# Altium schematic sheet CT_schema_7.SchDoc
size 369 x 207 mm
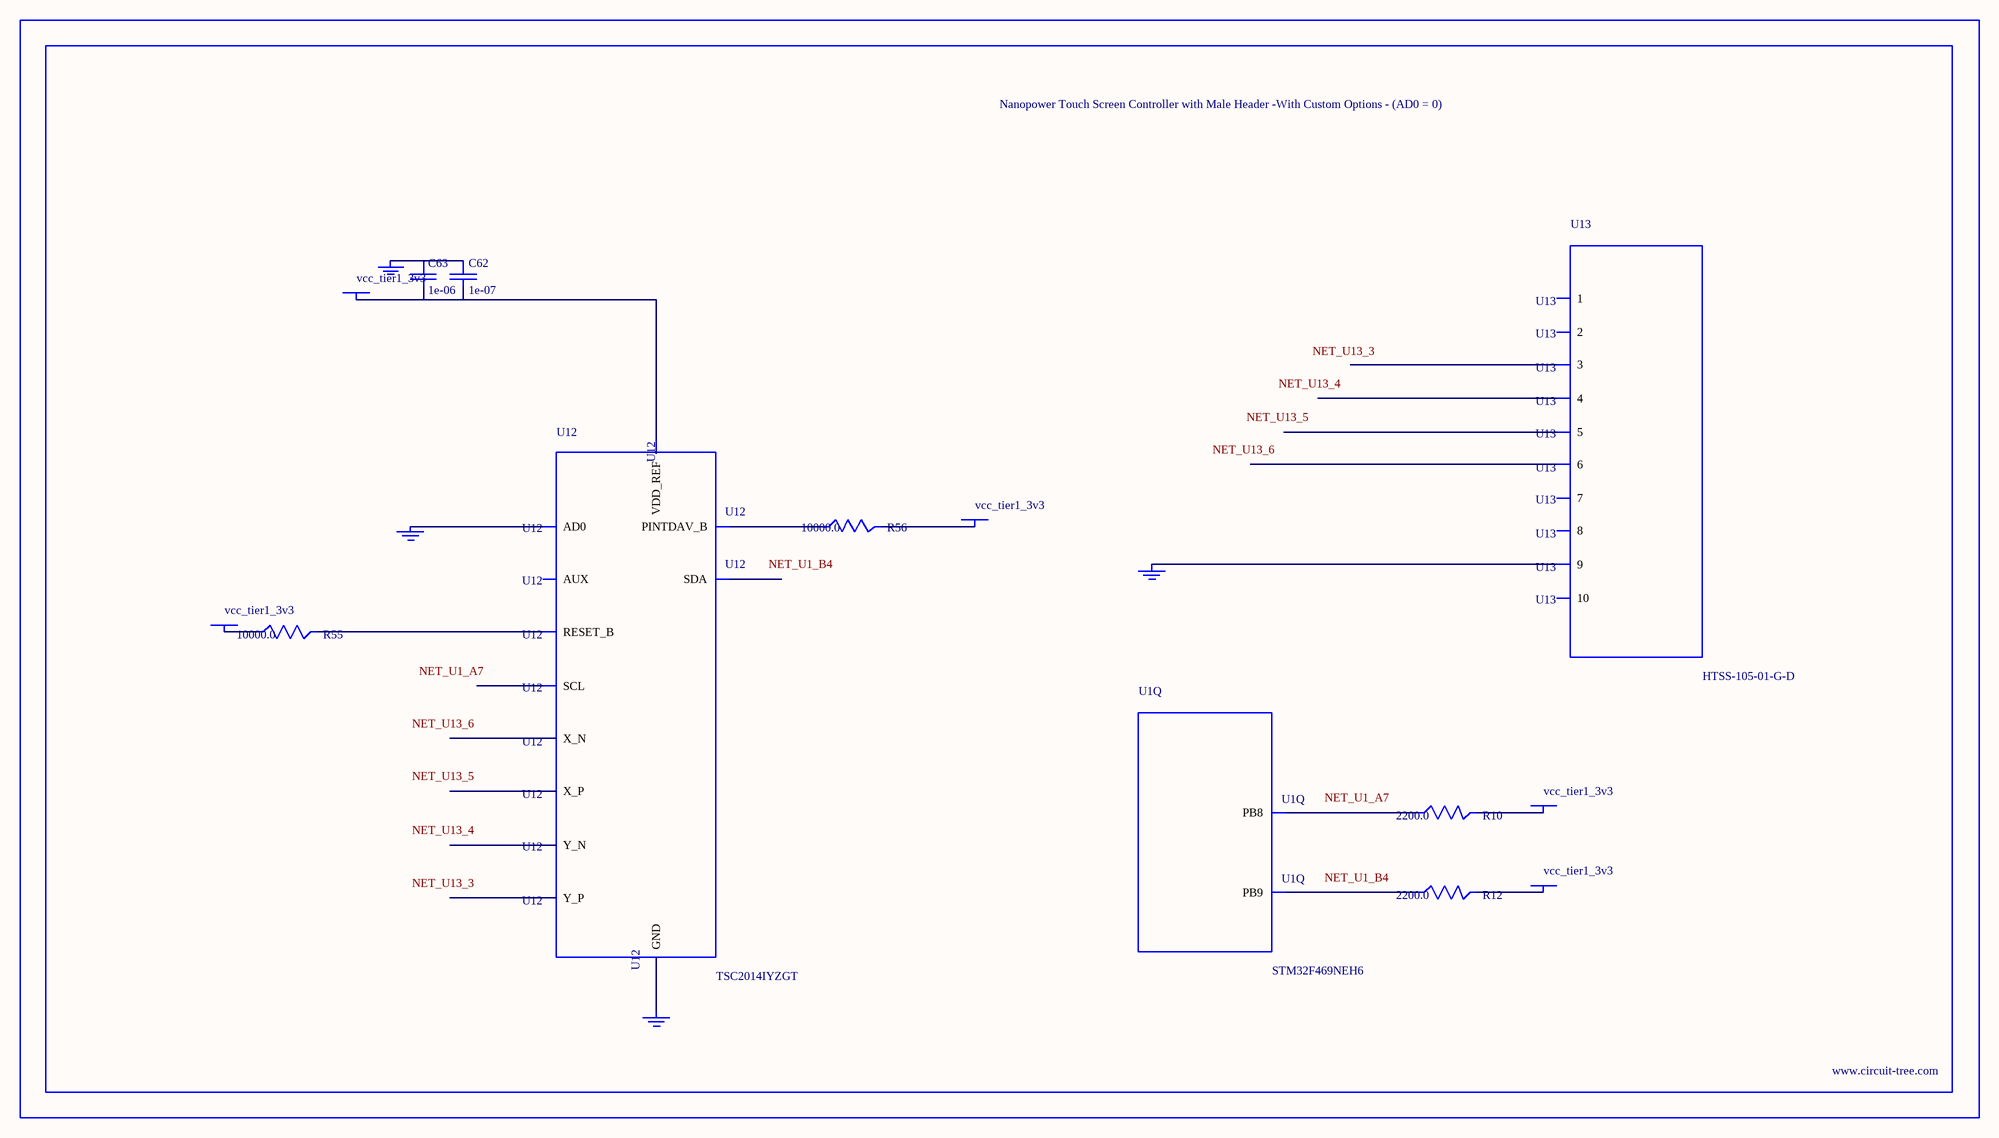
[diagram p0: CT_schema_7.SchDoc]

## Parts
BORDER6  (no value)
C62  1e-07  [C0402]
C63  1e-06  [C0603]
GND_INSTANCE_6_0  (no value)
GND_INSTANCE_6_1  (no value)
GND_INSTANCE_6_2  (no value)
GND_INSTANCE_6_3  (no value)
POWER_INSTANCE_6_0  vcc_tier1_3v3
POWER_INSTANCE_6_1  vcc_tier1_3v3
POWER_INSTANCE_6_2  vcc_tier1_3v3
POWER_INSTANCE_6_3  vcc_tier1_3v3
POWER_INSTANCE_6_4  vcc_tier1_3v3
R10  2200.0  [R0603]
R12  2200.0  [R0603]
R55  10000.0  [R0603]
R56  10000.0  [R0603]
U1  STM32F469NEH6  [TFBGA216]  (part Q of 17)
U12  TSC2014IYZGT  [TSC2014IYZGT]
U13  HTSS-105-01-G-D  [HTSS-105-01-G-D]

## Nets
NetC62_1: C62.1 C63.1 GND_INSTANCE_6_0.0(GND)
NetC62_2: C62.2 C63.2 POWER_INSTANCE_6_2.0(PWR) U12.A2(VDD_REF)
NetGND_INSTANCE_6_1_0: GND_INSTANCE_6_1.0(GND) U12.B2(AD0)
NetGND_INSTANCE_6_2_0: GND_INSTANCE_6_2.0(GND) U12.D2(GND)
NetGND_INSTANCE_6_3_0: GND_INSTANCE_6_3.0(GND) U13.9
NetPOWER_INSTANCE_6_0_0: POWER_INSTANCE_6_0.0(PWR) R55.1
NetPOWER_INSTANCE_6_1_0: POWER_INSTANCE_6_1.0(PWR) R56.2
NetPOWER_INSTANCE_6_3_0: POWER_INSTANCE_6_3.0(PWR) R10.2
NetPOWER_INSTANCE_6_4_0: POWER_INSTANCE_6_4.0(PWR) R12.2
NetR10_1: R10.1 U1.A7(PB8)
NetR12_1: R12.1 U1.B4(PB9)
NetR55_2: R55.2 U12.C2(RESET_B)
NetR56_1: R56.1 U12.B1(PINTDAV_B)

Not connected (* = marked no-connect by the designer): U12 A1(AUX) A3(X_P) B3(Y_P) C1(SDA) C3(X_N) D1(SCL) D3(Y_N); U13 1 2 3 4 5 6 7 8 10

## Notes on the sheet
- Labels drawn without touching a wire or pin: NET_U1_A7, NET_U1_B4, NET_U13_3, NET_U13_4, NET_U13_5, NET_U13_6

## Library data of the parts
BORDER6 = BORDER_PAGE6
C62 = C0402C104K3RACTU
C63 = C0603C105K3RACTU
GND_INSTANCE_6_0-GND_INSTANCE_6_3 = GND
POWER_INSTANCE_6_0-POWER_INSTANCE_6_4 = PWR
R10 R12 = RC0603JR-072K2L
R55 R56 = RC0603JR-0710KL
